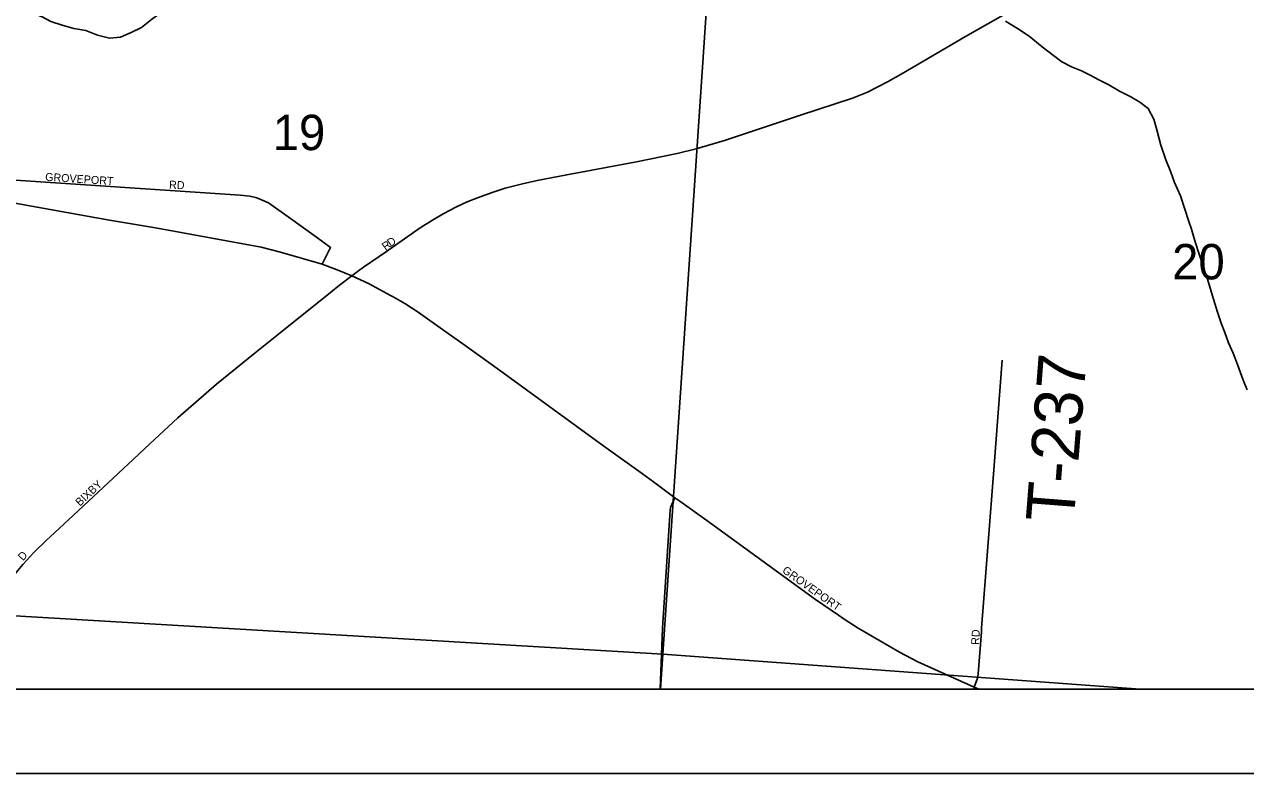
# Model space of a CAD drawing. Extents: x 0 to 34, y 0 to 22.
# Drawn here: x 4.15 to 5.595, y 14 to 14.886 of the extents above; entities that cross this region are included whole.
import ezdxf

# ---------------------------------------------------------------- set-up
doc = ezdxf.new("R2010")
doc.units = 0
for name, color, linetype in [('GM_X_City_Street', 7, 'Continuous'), ('GM_X_City_Street_Text', 7, 'Continuous'), ('GM_X_County_Road', 7, 'Continuous'), ('GM_X_Major_River', 7, 'Continuous'), ('GM_X_Minor_River', 7, 'Continuous'), ('GM_X_Section', 7, 'Continuous'), ('GM_X_Section_Text', 7, 'Continuous'), ('GM_X_Township', 7, 'Continuous'), ('GM_X_Township_Road', 7, 'Continuous'), ('GM_X_Township_Road_Text', 7, 'Continuous'), ('SH_Data', 7, 'Continuous')]:
    doc.layers.add(name, color=color, linetype=linetype)

msp = doc.modelspace()

# ---------------------------------------------------------------- linework, layer by layer
at = {"layer": 'GM_X_City_Street'}
for points in [[(4.5781, 14.6176), (4.581, 14.6196), (4.6181, 14.6455), (4.6324, 14.6545), (4.6453, 14.6619), (4.6611, 14.6704), (4.6736, 14.6762), (4.6858, 14.681), (4.7045, 14.6878), (4.7186, 14.6923), (4.7392, 14.6975), (4.7566, 14.7016), (4.7914, 14.7082), (4.8741, 14.7237), (4.922, 14.7335), (4.9447, 14.7391), (4.9782, 14.7488), (5.0683, 14.7786), (5.1296, 14.7988), (5.1475, 14.8059), (5.1719, 14.8184), (5.19, 14.8289), (5.2634, 14.8716), (5.3164, 14.9017)], [(4.0941, 14.6826), (4.0962, 14.6989), (4.0992, 14.7037), (4.1091, 14.7037), (4.4048, 14.6842), (4.4162, 14.6831), (4.4245, 14.6811), (4.4385, 14.675), (4.4646, 14.6567), (4.4952, 14.6343), (4.512, 14.6221), (4.5018, 14.6026)], [(4.0413, 14.6916), (4.0941, 14.6826), (4.2504, 14.6546), (4.3047, 14.6455), (4.4296, 14.6228), (4.4526, 14.6169), (4.5018, 14.6026), (4.5198, 14.5959), (4.5285, 14.5923), (4.5371, 14.5887)], [(4.5451, 14.5947), (4.5508, 14.5989), (4.5781, 14.6176)], [(4.2016, 14.3002), (4.2724, 14.3658), (4.2982, 14.3901), (4.3313, 14.4208), (4.377, 14.4605), (4.4227, 14.4978), (4.4522, 14.5213), (4.5117, 14.5689), (4.5224, 14.5778), (4.5371, 14.5887)], [(4.5371, 14.5887), (4.5451, 14.5947)], [(4.5371, 14.5887), (4.5567, 14.5796), (4.583, 14.5655), (4.5861, 14.5637), (4.5997, 14.5559), (4.6158, 14.5457), (4.6444, 14.5254), (4.6713, 14.5062), (4.7117, 14.4771), (4.8352, 14.3874), (4.8766, 14.3576)], [(4.9253, 14.3221), (4.9573, 14.2994), (5.086, 14.2059), (5.113, 14.1873), (5.1198, 14.1826), (5.1364, 14.1718), (5.1852, 14.1437), (5.207, 14.132), (5.2738, 14.1021), (5.2795, 14.1)], [(4.116, 14.2057), (4.1198, 14.2116), (4.1309, 14.2268), (4.1397, 14.238), (4.1475, 14.2474), (4.1608, 14.2615), (4.1756, 14.276), (4.18, 14.2801)], [(5.2738, 14.1021), (5.2775, 14.1129), (5.2783, 14.1181), (5.2822, 14.1676)], [(5.2733, 14.1), (5.2738, 14.1021)]]:
    msp.add_lwpolyline(points, dxfattribs=at)
at = {"layer": 'GM_X_County_Road'}
for points in [[(4.8766, 14.3576), (4.8942, 14.3449), (4.9194, 14.3263), (4.9253, 14.3221)], [(4.18, 14.2801), (4.2016, 14.3002)]]:
    msp.add_lwpolyline(points, dxfattribs=at)
at = {"layer": 'GM_X_Major_River'}
msp.add_lwpolyline([(4.3358, 14.9134), (4.3237, 14.9063), (4.3119, 14.9006), (4.2998, 14.8919), (4.2881, 14.8824), (4.276, 14.8764), (4.2631, 14.8711), (4.2502, 14.8699), (4.2362, 14.8734), (4.2222, 14.8787), (4.2082, 14.8814), (4.1943, 14.8852), (4.181, 14.8897), (4.1704, 14.8951), (4.1602, 14.8989), (4.1462, 14.903)], dxfattribs=at)
at = {"layer": 'GM_X_Minor_River'}
msp.add_lwpolyline([(5.3107, 14.8901), (5.3249, 14.8811), (5.3388, 14.8721), (5.3541, 14.8597), (5.3675, 14.8493), (5.3776, 14.8419), (5.3889, 14.836), (5.4006, 14.8313), (5.4111, 14.8262), (5.4212, 14.8207), (5.4332, 14.8148), (5.4456, 14.807), (5.4591, 14.8003), (5.4699, 14.7941), (5.4797, 14.7867), (5.4863, 14.7741), (5.4898, 14.7615), (5.4948, 14.7432), (5.5006, 14.726), (5.5064, 14.7115), (5.5107, 14.6993), (5.518, 14.6832), (5.5231, 14.6676), (5.5274, 14.6542), (5.531, 14.6439), (5.5342, 14.6329), (5.5385, 14.6192), (5.5428, 14.6062), (5.5457, 14.5963), (5.5497, 14.5848), (5.5543, 14.57), (5.5586, 14.5558), (5.5619, 14.5459), (5.5662, 14.5326), (5.5702, 14.5215), (5.5749, 14.5093), (5.5804, 14.4971), (5.5854, 14.4837), (5.5891, 14.4738), (5.593, 14.4635), (5.5967, 14.4539)], dxfattribs=at)
at = {"layer": 'GM_X_Section'}
for p, q in [((3.9572, 14.1), (4.9025, 14.1)), ((4.9025, 14.1), (5.4703, 14.1)), ((5.4703, 14.1), (5.9313, 14.1))]:
    msp.add_line(p, q, dxfattribs=at)
msp.add_lwpolyline([(4.037, 15.2488), (4.9746, 15.1686), (4.9053, 14.1412), (3.9642, 14.1968), (4.0318, 15.1906)], close=True, dxfattribs=at)
for points in [[(5.9313, 14.1), (6.0038, 15.0886), (4.9746, 15.1686), (4.9053, 14.1412), (5.4703, 14.1)], [(4.9025, 14.1), (4.9053, 14.1412), (3.9642, 14.1968), (3.9626, 14.1817), (3.9572, 14.1)], [(5.4703, 14.1), (4.9053, 14.1412), (4.9025, 14.1)]]:
    msp.add_lwpolyline(points, dxfattribs=at)
at = {"layer": 'GM_X_Township'}
msp.add_lwpolyline([(3.9541, 14.1), (9.4, 14.1), (9.4, 17.8295)], dxfattribs=at)
at = {"layer": 'GM_X_Township_Road'}
for points in [[(5.2822, 14.1676), (5.2825, 14.172), (5.2972, 14.3645), (5.307, 14.4889)], [(4.902, 14.1), (4.905, 14.172), (4.9137, 14.3117), (4.9142, 14.3145), (4.9194, 14.3263)]]:
    msp.add_lwpolyline(points, dxfattribs=at)
at = {"layer": 'SH_Data'}
for p, q in [((2.6, 14.1), (9.4, 14.1)), ((2.5, 14), (9.5, 14))]:
    msp.add_line(p, q, dxfattribs=at)

# ---------------------------------------------------------------- texts
at = {"layer": 'GM_X_City_Street_Text'}
for s, rotation, p in [('GROVEPORT', 356.3082, (4.1739, 14.7012)), ('RD', 356.9776, (4.3206, 14.692)), ('R', 35.8059, (4.577, 14.6182)), ('D', 34.8237, (4.583, 14.6226)), ('BIXBY', 43.0883, (4.2152, 14.3156)), ('D', 48.0307, (4.1479, 14.251)), ('GROVEPORT', 324.7825, (5.0457, 14.2384)), ('RD', 86.9884, (5.2795, 14.152))]:
    msp.add_text(s, height=0.00947, rotation=rotation, dxfattribs=at).set_placement(p)
at = {"layer": 'GM_X_Section_Text'}
for s, p in [('19', (4.4434, 14.7374)), ('20', (5.508, 14.5845))]:
    msp.add_text(s, height=0.04186, rotation=0, dxfattribs=at).set_placement(p)
at = {"layer": 'GM_X_Township_Road_Text'}
msp.add_text('T-237', height=0.05682, rotation=85.5148, dxfattribs=at).set_placement((5.3914, 14.2959))

doc.saveas('drawing.dxf')
